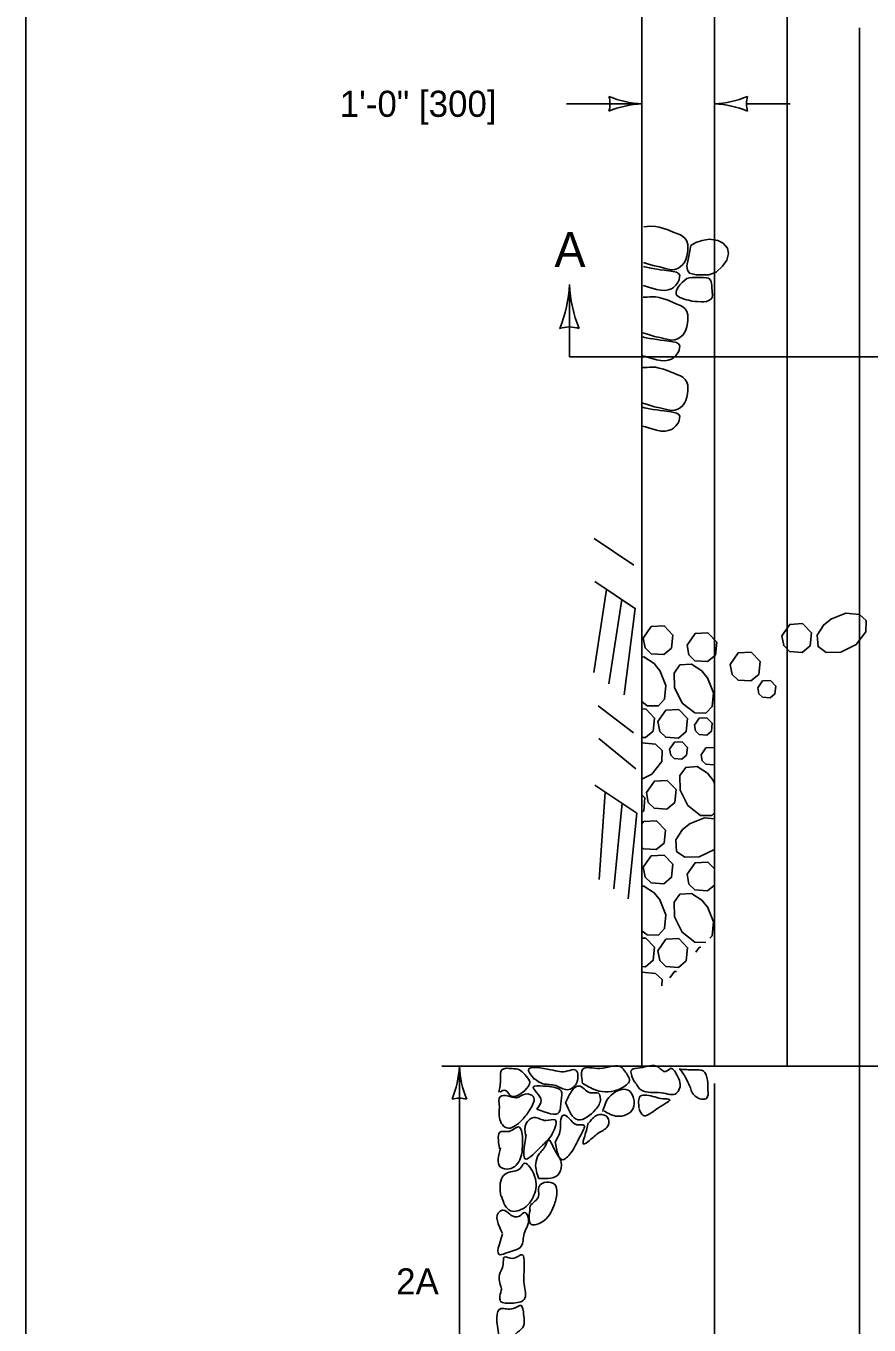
# Model space of a CAD drawing. Extents: x 49991.4 to 50021, y 49987.6 to 50011.4.
# Drawn here: x 49999.384 to 50001.321, y 49993.444 to 49996.429 of the extents above; entities that cross this region are included whole.
import ezdxf

# ---------------------------------------------------------------- set-up
doc = ezdxf.new("R2010")
doc.units = 0
for name, color, linetype in [('Level 1', 7, 'Continuous'), ('Level 2', 7, 'Continuous'), ('Level 3', 7, 'Continuous'), ('Level 6', 7, 'Continuous')]:
    doc.layers.add(name, color=color, linetype=linetype)

msp = doc.modelspace()

# ---------------------------------------------------------------- linework, layer by layer
at = {"layer": 'Level 1'}
for p, q in [((50001.1324, 49997.6503), (50001.1324, 49994.0392)), ((50000.9657, 49997.2058), (50000.9657, 49994.0392)), ((50000.7991, 49997.1899), (50000.7991, 49994.0392)), ((50000.7806, 49995.1902), (50000.6892, 49995.2514)), ((50000.7844, 49995.0903), (50000.6904, 49995.1528)), ((50000.7175, 49995.1348), (50000.6885, 49994.9441)), ((50000.7528, 49995.1114), (50000.7233, 49994.9177)), ((50000.7833, 49995.091), (50000.758, 49994.8927)), ((50000.7796, 49994.805), (50000.6986, 49994.8671)), ((50000.7848, 49994.7221), (50000.7001, 49994.7922)), ((50000.9629, 49994.6962), (50000.9657, 49994.6891)), ((50000.7874, 49994.6204), (50000.691, 49994.685)), ((50000.7146, 49994.6692), (50000.7007, 49994.4685)), ((50000.7533, 49994.6432), (50000.7344, 49994.4465)), ((50000.7874, 49994.6204), (50000.767, 49994.4241)), ((50000.7991, 49994.0392), (50001.7992, 49994.0392))]:
    msp.add_line(p, q, dxfattribs=at)
for points in [[(49999.3835, 49998.9992), (50016.7501, 49998.9992), (50016.7501, 49987.7988), (49999.3835, 49987.7988)], [(50000.9081, 49995.8509), (50000.9024, 49995.8491), (50000.8972, 49995.8453), (50000.8913, 49995.8404), (50000.8864, 49995.8348), (50000.8825, 49995.8292), (50000.8788, 49995.8225), (50000.878, 49995.8171), (50000.878, 49995.8133), (50000.8795, 49995.8104), (50000.8827, 49995.8079), (50000.8862, 49995.8054), (50000.8908, 49995.8037), (50000.8963, 49995.8014), (50000.9017, 49995.8001), (50000.9071, 49995.7992), (50000.9135, 49995.7974), (50000.9206, 49995.796), (50000.9265, 49995.796), (50000.9349, 49995.7956), (50000.9411, 49995.7956), (50000.9477, 49995.7965), (50000.9541, 49995.7992), (50000.9581, 49995.8023), (50000.9603, 49995.8059), (50000.9615, 49995.8099), (50000.9605, 49995.8204), (50000.9598, 49995.8278), (50000.9593, 49995.8332), (50000.9583, 49995.8424), (50000.9561, 49995.8462), (50000.9526, 49995.8496), (50000.9467, 49995.8511), (50000.9396, 49995.8513), (50000.9305, 49995.8516), (50000.9214, 49995.8516), (50000.9145, 49995.8516)]]:
    msp.add_lwpolyline(points, close=True, dxfattribs=at)
for points in [[(50000.8031, 49995.9682), (50000.8113, 49995.9684), (50000.8172, 49995.9691), (50000.8298, 49995.9689), (50000.8389, 49995.9671), (50000.8487, 49995.9644), (50000.8566, 49995.9617), (50000.862, 49995.9595), (50000.8709, 49995.9559), (50000.8793, 49995.9523), (50000.8879, 49995.9492), (50000.8928, 49995.9458), (50000.8987, 49995.9411), (50000.9022, 49995.9348), (50000.9041, 49995.9274), (50000.9046, 49995.9225), (50000.9044, 49995.9154), (50000.9039, 49995.9082), (50000.9019, 49995.9004), (50000.9002, 49995.8927), (50000.8972, 49995.8878), (50000.8926, 49995.8811), (50000.8869, 49995.8759), (50000.8817, 49995.8724), (50000.8743, 49995.8701), (50000.8672, 49995.8695), (50000.8527, 49995.8724), (50000.8401, 49995.8757), (50000.8276, 49995.8782), (50000.8138, 49995.8824), (50000.8025, 49995.8858)], [(50000.954, 49995.9395), (50000.9373, 49995.9368), (50000.923, 49995.9319), (50000.9116, 49995.925), (50000.9067, 49995.9006), (50000.9023, 49995.8786), (50000.9038, 49995.8683), (50000.9082, 49995.8616), (50000.924, 49995.858), (50000.953, 49995.858), (50000.9693, 49995.8638), (50000.9845, 49995.8773), (50000.9944, 49995.8916), (50000.9983, 49995.9064), (50000.9954, 49995.9189), (50000.9855, 49995.9306), (50000.9732, 49995.9368), (50000.954, 49995.9395)], [(50000.8025, 49995.8765), (50000.8052, 49995.8757), (50000.816, 49995.8735), (50000.8244, 49995.8721), (50000.8337, 49995.8708), (50000.8411, 49995.8695), (50000.85, 49995.8686), (50000.866, 49995.8663), (50000.8783, 49995.8636), (50000.8827, 49995.8609), (50000.8862, 49995.8565), (50000.8857, 49995.852), (50000.8845, 49995.8459), (50000.8813, 49995.8399), (50000.8768, 49995.8341), (50000.8719, 49995.8287), (50000.867, 49995.8256), (50000.8596, 49995.8233), (50000.8527, 49995.822), (50000.8428, 49995.8222), (50000.8323, 49995.8242), (50000.8251, 49995.8265), (50000.816, 49995.8287), (50000.8069, 49995.8318), (50000.8021, 49995.833)], [(50000.8019, 49995.8062), (50000.8029, 49995.8064), (50000.8113, 49995.8066), (50000.8172, 49995.8073), (50000.8298, 49995.807), (50000.8389, 49995.8052), (50000.8487, 49995.8026), (50000.8566, 49995.7999), (50000.862, 49995.7976), (50000.8709, 49995.794), (50000.8793, 49995.7905), (50000.8879, 49995.7873), (50000.8928, 49995.784), (50000.8987, 49995.7793), (50000.9022, 49995.773), (50000.9041, 49995.7656), (50000.9046, 49995.7607), (50000.9044, 49995.7535), (50000.9039, 49995.7464), (50000.9019, 49995.7385), (50000.9002, 49995.7309), (50000.8972, 49995.726), (50000.8926, 49995.7193), (50000.8869, 49995.7141), (50000.8817, 49995.7105), (50000.8743, 49995.7083), (50000.8672, 49995.7076), (50000.8527, 49995.7105), (50000.8401, 49995.7139), (50000.8276, 49995.7163), (50000.8138, 49995.7206), (50000.8013, 49995.7244)], [(50000.8013, 49995.715), (50000.8052, 49995.7139), (50000.816, 49995.7116), (50000.8244, 49995.7103), (50000.8337, 49995.709), (50000.8411, 49995.7076), (50000.85, 49995.7067), (50000.866, 49995.7045), (50000.8783, 49995.7018), (50000.8827, 49995.6991), (50000.8862, 49995.6946), (50000.8857, 49995.6902), (50000.8845, 49995.6841), (50000.8813, 49995.6781), (50000.8768, 49995.6722), (50000.8719, 49995.6669), (50000.867, 49995.6637), (50000.8596, 49995.6615), (50000.8527, 49995.6602), (50000.8428, 49995.6604), (50000.8323, 49995.6624), (50000.8251, 49995.6646), (50000.816, 49995.6669), (50000.8069, 49995.67), (50000.8009, 49995.6715)], [(50000.8007, 49995.6442), (50000.8029, 49995.6445), (50000.8113, 49995.6447), (50000.8172, 49995.6454), (50000.8298, 49995.6452), (50000.8389, 49995.6434), (50000.8487, 49995.6407), (50000.8566, 49995.638), (50000.862, 49995.6358), (50000.8709, 49995.6322), (50000.8793, 49995.6286), (50000.8879, 49995.6255), (50000.8928, 49995.6221), (50000.8987, 49995.6174), (50000.9022, 49995.6112), (50000.9041, 49995.6038), (50000.9046, 49995.5988), (50000.9044, 49995.5917), (50000.9039, 49995.5845), (50000.9019, 49995.5767), (50000.9002, 49995.5691), (50000.8972, 49995.5641), (50000.8926, 49995.5574), (50000.8869, 49995.5523), (50000.8817, 49995.5487), (50000.8743, 49995.5464), (50000.8672, 49995.5458), (50000.8527, 49995.5487), (50000.8401, 49995.552), (50000.8276, 49995.5545), (50000.8138, 49995.5588), (50000.8012, 49995.5626), (50000.8001, 49995.563)], [(50000.8, 49995.5536), (50000.8052, 49995.552), (50000.816, 49995.5498), (50000.8244, 49995.5485), (50000.8337, 49995.5471), (50000.8411, 49995.5458), (50000.85, 49995.5449), (50000.866, 49995.5426), (50000.8783, 49995.54), (50000.8827, 49995.5373), (50000.8862, 49995.5328), (50000.8857, 49995.5283), (50000.8845, 49995.5223), (50000.8813, 49995.5162), (50000.8768, 49995.5104), (50000.8719, 49995.505), (50000.867, 49995.5019), (50000.8596, 49995.4997), (50000.8527, 49995.4983), (50000.8428, 49995.4985), (50000.8323, 49995.5006), (50000.8251, 49995.5028), (50000.816, 49995.505), (50000.8069, 49995.5082), (50000.7997, 49995.5099)], [(50001.2331, 49995.0664), (50001.2676, 49995.0801), (50001.2993, 49995.0773), (50001.3144, 49995.063), (50001.3139, 49995.0373), (50001.291, 49995.0081), (50001.2557, 49994.9904), (50001.2224, 49994.9898), (50001.2037, 49995.0032), (50001.2019, 49995.0297), (50001.2171, 49995.0534), (50001.2345, 49995.0673)], [(50000.8019, 49995.0231), (50000.8203, 49995.0493), (50000.8497, 49995.051), (50000.8702, 49995.0298), (50000.8672, 49995.0001), (50000.8491, 49994.9849), (50000.82, 49994.987), (50000.8063, 49995.0003), (50000.8019, 49995.0231)], [(50001.1203, 49995.0283), (50001.1387, 49995.0545), (50001.1681, 49995.0562), (50001.1886, 49995.0349), (50001.1857, 49995.0052), (50001.1675, 49994.9901), (50001.1384, 49994.9922), (50001.1247, 49995.0055), (50001.1203, 49995.0283)], [(50000.9027, 49995.007), (50000.9211, 49995.0333), (50000.9506, 49995.035), (50000.971, 49995.0137), (50000.9681, 49994.984), (50000.9499, 49994.9689), (50000.9208, 49994.971), (50000.9071, 49994.9842), (50000.9027, 49995.007)], [(50001.002, 49994.9624), (50001.0204, 49994.9887), (50001.0499, 49994.9903), (50001.0704, 49994.9691), (50001.0674, 49994.9394), (50001.0492, 49994.9243), (50001.0201, 49994.9264), (50001.0065, 49994.9396), (50001.002, 49994.9624)], [(50000.7991, 49994.9793), (50000.8035, 49994.9796), (50000.8272, 49994.9644), (50000.8411, 49994.947)], [(50000.9496, 49994.9316), (50000.9632, 49994.8971), (50000.9605, 49994.8654), (50000.9462, 49994.8504), (50000.9205, 49994.8509), (50000.8912, 49994.8737), (50000.8736, 49994.9091), (50000.873, 49994.9423), (50000.8863, 49994.9611), (50000.9128, 49994.9629), (50000.9366, 49994.9477), (50000.9505, 49994.9303)], [(50000.8402, 49994.9484), (50000.8539, 49994.9139), (50000.8512, 49994.8822), (50000.8368, 49994.8671), (50000.8111, 49994.8676), (50000.7991, 49994.877)], [(50001.0654, 49994.9087), (50001.0764, 49994.9244), (50001.0941, 49994.9254), (50001.1064, 49994.9127), (50001.1046, 49994.8948), (50001.0937, 49994.8858), (50001.0762, 49994.887), (50001.068, 49994.895), (50001.0654, 49994.9087)], [(50000.7991, 49994.8597), (50000.8076, 49994.8602), (50000.8281, 49994.839), (50000.8251, 49994.8092), (50000.8069, 49994.7941), (50000.7991, 49994.7947)], [(50000.8356, 49994.8312), (50000.854, 49994.8574), (50000.8835, 49994.8591), (50000.904, 49994.8379), (50000.901, 49994.8081), (50000.8828, 49994.793), (50000.8537, 49994.7951), (50000.8401, 49994.8084), (50000.8356, 49994.8312)], [(50000.9195, 49994.8231), (50000.9306, 49994.8388), (50000.9482, 49994.8398), (50000.9605, 49994.8271), (50000.9587, 49994.8092), (50000.9478, 49994.8002), (50000.9304, 49994.8014), (50000.9222, 49994.8094), (50000.9195, 49994.8231)], [(50000.7991, 49994.7819), (50000.8301, 49994.7792), (50000.8452, 49994.7649), (50000.8447, 49994.7392), (50000.8218, 49994.7099), (50000.7991, 49994.6986)], [(50000.8624, 49994.7677), (50000.8735, 49994.7835), (50000.8912, 49994.7845), (50000.9034, 49994.7717), (50000.9017, 49994.7539), (50000.8908, 49994.7448), (50000.8733, 49994.7461), (50000.8651, 49994.754), (50000.8624, 49994.7677)], [(50000.9351, 49994.7548), (50000.9461, 49994.7705), (50000.9638, 49994.7715), (50000.9657, 49994.7695)], [(50000.9657, 49994.7338), (50000.9634, 49994.7318), (50000.946, 49994.7331), (50000.9377, 49994.7411), (50000.9351, 49994.7547)], [(50000.9657, 49994.6215), (50000.9596, 49994.615), (50000.9338, 49994.6155), (50000.9046, 49994.6383), (50000.887, 49994.6737), (50000.8864, 49994.7069), (50000.8997, 49994.7257), (50000.9262, 49994.7275), (50000.9499, 49994.7123), (50000.9638, 49994.6948)], [(50000.8091, 49994.6681), (50000.8275, 49994.6944), (50000.857, 49994.696), (50000.8774, 49994.6748), (50000.8745, 49994.6451), (50000.8563, 49994.63), (50000.8272, 49994.6321), (50000.8135, 49994.6453), (50000.8091, 49994.6681)], [(50000.7991, 49994.6627), (50000.8059, 49994.6556), (50000.803, 49994.6258), (50000.7991, 49994.6226)], [(50000.7991, 49994.5957), (50000.8029, 49994.6012), (50000.8324, 49994.6029), (50000.8529, 49994.5817), (50000.8499, 49994.5519), (50000.8317, 49994.5368), (50000.8026, 49994.5389), (50000.7991, 49994.5424)], [(50000.9083, 49994.5959), (50000.9428, 49994.6096), (50000.9657, 49994.6076)], [(50000.9657, 49994.5374), (50000.9308, 49994.52), (50000.8975, 49994.5194), (50000.8788, 49994.5327), (50000.877, 49994.5592), (50000.8922, 49994.5829), (50000.9097, 49994.5968)], [(50000.8019, 49994.4964), (50000.8203, 49994.5227), (50000.8497, 49994.5244), (50000.8702, 49994.5031), (50000.8672, 49994.4734), (50000.8491, 49994.4583), (50000.82, 49994.4604), (50000.8063, 49994.4736), (50000.8019, 49994.4964)], [(50000.9027, 49994.4804), (50000.9211, 49994.5066), (50000.9506, 49994.5083), (50000.9657, 49994.4925)], [(50000.7991, 49994.4526), (50000.8035, 49994.4529), (50000.8272, 49994.4377), (50000.8411, 49994.4203)], [(50000.9657, 49994.4554), (50000.9499, 49994.4422), (50000.9208, 49994.4443), (50000.9071, 49994.4576), (50000.9027, 49994.4804)], [(50000.8402, 49994.4217), (50000.8539, 49994.3872), (50000.8512, 49994.3555), (50000.8368, 49994.3404), (50000.8111, 49994.3409), (50000.7991, 49994.3504)], [(50000.9456, 49994.3237), (50000.9205, 49994.3242), (50000.8912, 49994.3471), (50000.8736, 49994.3824), (50000.873, 49994.4157), (50000.8863, 49994.4344), (50000.9128, 49994.4362), (50000.9366, 49994.421), (50000.9505, 49994.4036)], [(50000.9496, 49994.405), (50000.9632, 49994.3705), (50000.9605, 49994.3388), (50000.9553, 49994.3333)], [(50000.7991, 49994.3331), (50000.8076, 49994.3335), (50000.8281, 49994.3123), (50000.8251, 49994.2826), (50000.8069, 49994.2675), (50000.7991, 49994.268)], [(50000.8356, 49994.3045), (50000.854, 49994.3307), (50000.8835, 49994.3324), (50000.904, 49994.3112), (50000.901, 49994.2815), (50000.8828, 49994.2663), (50000.8537, 49994.2684), (50000.8401, 49994.2817), (50000.8356, 49994.3045)], [(50000.9228, 49994.3012), (50000.9306, 49994.3121), (50000.9341, 49994.3123)], [(50000.7991, 49994.2552), (50000.8301, 49994.2525), (50000.8452, 49994.2382), (50000.8449, 49994.2239)], [(50000.863, 49994.2419), (50000.8735, 49994.2568), (50000.8783, 49994.2571)]]:
    msp.add_lwpolyline(points, dxfattribs=at)
for points in [[(50000.4702, 49993.9795), (50000.4743, 49994.0101), (50000.4771, 49994.0309), (50000.5007, 49994.0337), (50000.5174, 49994.0309), (50000.5299, 49994.0198), (50000.541, 49994.0031), (50000.5299, 49993.9836), (50000.4952, 49993.9725), (50000.4855, 49993.9836), (50000.473, 49993.9795)], [(50000.5521, 49994.0087), (50000.5382, 49994.0309), (50000.5896, 49994.0309), (50000.6285, 49994.0281), (50000.6452, 49994.0309), (50000.6508, 49994.0059), (50000.6271, 49993.985), (50000.6008, 49993.9948), (50000.5716, 49993.9989), (50000.5521, 49994.0101)], [(50000.6619, 49994.002), (50000.6633, 49994.0326), (50000.7022, 49994.034), (50000.7536, 49994.0354), (50000.7591, 49994.0284), (50000.7702, 49994.0062), (50000.7508, 49993.9881), (50000.6938, 49993.984), (50000.6619, 49994.0006)], [(50000.7814, 49994.0032), (50000.7758, 49994.031), (50000.7939, 49994.0352), (50000.8369, 49994.0366), (50000.8536, 49994.0269), (50000.8647, 49994.0338), (50000.8814, 49994.0144), (50000.8869, 49993.9977), (50000.8786, 49993.9768), (50000.8439, 49993.9782), (50000.798, 49993.9838), (50000.7827, 49994.0032)], [(50000.8842, 49994.0324), (50000.9189, 49994.031), (50000.9397, 49994.0282), (50000.9494, 49994.0074), (50000.9508, 49993.9838), (50000.9481, 49993.9657), (50000.9217, 49993.9699), (50000.9092, 49993.9921), (50000.8994, 49994.013), (50000.8869, 49994.0324)], [(50000.4716, 49993.9446), (50000.4743, 49993.9696), (50000.4896, 49993.971), (50000.5105, 49993.9668), (50000.5313, 49993.9751), (50000.5494, 49993.9696), (50000.5424, 49993.9404), (50000.523, 49993.9154), (50000.4882, 49993.8973), (50000.4757, 49993.9085), (50000.4716, 49993.9432)], [(50000.5577, 49993.9407), (50000.5674, 49993.9602), (50000.5577, 49993.9782), (50000.5494, 49993.9907), (50000.573, 49993.9935), (50000.5966, 49993.9907), (50000.6133, 49993.9824), (50000.6133, 49993.9602), (50000.6091, 49993.9338), (50000.5577, 49993.9407)], [(50000.623, 49993.9546), (50000.6327, 49993.9741), (50000.6411, 49993.9866), (50000.6536, 49993.9935), (50000.6799, 49993.9782), (50000.6994, 49993.9768), (50000.7036, 49993.9643), (50000.6924, 49993.9393), (50000.6522, 49993.9157), (50000.623, 49993.956)], [(50000.7091, 49993.9352), (50000.723, 49993.9671), (50000.7675, 49993.9838), (50000.7786, 49993.9421), (50000.7425, 49993.924), (50000.7119, 49993.9366)], [(50000.7925, 49993.9421), (50000.7952, 49993.9699), (50000.8286, 49993.9685), (50000.848, 49993.9643), (50000.8619, 49993.9629), (50000.8369, 49993.9435), (50000.8008, 49993.9268), (50000.7925, 49993.9407)], [(50000.5313, 49993.881), (50000.5327, 49993.9074), (50000.5507, 49993.9213), (50000.5785, 49993.9143), (50000.5994, 49993.9157), (50000.5938, 49993.8852), (50000.5674, 49993.8546), (50000.5327, 49993.8254), (50000.5327, 49993.8824)], [(50000.5994, 49993.8643), (50000.6119, 49993.8963), (50000.6119, 49993.9115), (50000.6188, 49993.9268), (50000.6313, 49993.9199), (50000.6494, 49993.9046), (50000.6661, 49993.9032), (50000.6591, 49993.8824), (50000.6383, 49993.8435), (50000.6174, 49993.824), (50000.5994, 49993.8657)], [(50000.6772, 49993.9088), (50000.7022, 49993.9282), (50000.7202, 49993.9213), (50000.7216, 49993.9032), (50000.7008, 49993.8865), (50000.6786, 49993.8685), (50000.6647, 49993.8602), (50000.6674, 49993.8782), (50000.6758, 49993.9088)], [(50000.4716, 49993.849), (50000.4757, 49993.8893), (50000.4938, 49993.8893), (50000.5174, 49993.899), (50000.523, 49993.8865), (50000.5244, 49993.856), (50000.5202, 49993.8282), (50000.4938, 49993.8032), (50000.4743, 49993.8074), (50000.4743, 49993.8518)], [(50000.5619, 49993.7808), (50000.5549, 49993.8155), (50000.5619, 49993.8364), (50000.5771, 49993.8558), (50000.5841, 49993.8697), (50000.598, 49993.8475), (50000.6133, 49993.8183), (50000.6091, 49993.7933), (50000.5619, 49993.7808)], [(50000.4747, 49993.7402), (50000.4788, 49993.7847), (50000.49, 49993.7944), (50000.5191, 49993.8041), (50000.5275, 49993.8152), (50000.5497, 49993.793), (50000.5525, 49993.7471), (50000.5288, 49993.7138), (50000.4969, 49993.7069), (50000.4761, 49993.7402)], [(50000.5424, 49993.7058), (50000.541, 49993.7141), (50000.5605, 49993.7377), (50000.5633, 49993.7641), (50000.598, 49993.7683), (50000.6035, 49993.7475), (50000.5966, 49993.7183), (50000.5688, 49993.6808), (50000.5452, 49993.6752), (50000.541, 49993.7072)], [(50000.4785, 49993.6544), (50000.473, 49993.7058), (50000.4799, 49993.7086), (50000.4952, 49993.6989), (50000.5174, 49993.6947), (50000.5299, 49993.703), (50000.5382, 49993.6891), (50000.5285, 49993.6544), (50000.5216, 49993.6252), (50000.491, 49993.6113), (50000.473, 49993.6058), (50000.4785, 49993.653)], [(50000.4757, 49993.5294), (50000.4716, 49993.5599), (50000.4799, 49993.5835), (50000.4827, 49993.6002), (50000.5021, 49993.5974), (50000.5244, 49993.6058), (50000.5285, 49993.5863), (50000.5285, 49993.5377), (50000.5285, 49993.503), (50000.4994, 49993.4946), (50000.4743, 49993.4988), (50000.4771, 49993.528)], [(50000.4702, 49993.4196), (50000.4757, 49993.4821), (50000.5035, 49993.4821), (50000.5216, 49993.4891), (50000.5271, 49993.4682), (50000.5271, 49993.4419), (50000.4994, 49993.4113), (50000.4924, 49993.3904), (50000.4702, 49993.3918), (50000.4702, 49993.4196)]]:
    msp.add_spline(points, degree=3, dxfattribs=at)
at = {"layer": 'Level 3'}
for p, q in [((50000.6257, 49996.2507), (50000.7991, 49996.2507)), ((50001.0393, 49996.2507), (50001.1393, 49996.2507)), ((50000.3394, 49994.0392), (50000.9257, 49994.0392)), ((50000.3794, 49993.0499), (50000.3794, 49994.0392)), ((50000.9657, 49993.9992), (50000.9657, 49992.8309))]:
    msp.add_line(p, q, dxfattribs=at)
for centre, radius, start, end in [((50000.8082, 49996.4729), 0.2223, 247.456, 267.6395), ((50000.6709, 49996.2507), 0.0548, 342.1388, 17.8612), ((50000.8106, 49996.018), 0.233, 92.8273, 112.0772), ((50000.9566, 49996.4729), 0.2223, 272.3605, 292.544), ((50000.9543, 49996.018), 0.233, 67.9228, 87.1727), ((50001.094, 49996.2507), 0.0548, 162.1388, 197.8612), ((50000.1573, 49994.0484), 0.2223, 337.456, 357.6395), ((50000.6122, 49994.0507), 0.233, 182.8273, 202.0772), ((50000.3794, 49993.911), 0.0548, 72.1388, 107.8612)]:
    msp.add_arc(centre, radius, start, end, dxfattribs=at)
at = {"layer": 'Level 6'}
for p, q in [((50001.2991, 49993.0109), (50001.2991, 49996.4249)), ((50000.6323, 49995.669), (50000.6323, 49995.8357)), ((50000.6323, 49995.669), (50001.9659, 49995.669))]:
    msp.add_line(p, q, dxfattribs=at)
for centre, radius, start, end in [((50000.3362, 49995.8479), 0.2964, 337.456, 357.6395), ((50000.9426, 49995.851), 0.3107, 182.8273, 202.0772), ((50000.6323, 49995.6648), 0.073, 72.1388, 107.8612)]:
    msp.add_arc(centre, radius, start, end, dxfattribs=at)

# ---------------------------------------------------------------- texts
at = {"layer": 'Level 2'}
for s, height, p in [('1\'-0" [300]', 0.06, (50000.1045, 49996.2207)), ('A', 0.08, (50000.598, 49995.8757)), ('2A', 0.06, (50000.2341, 49993.5146))]:
    msp.add_text(s, height=height, dxfattribs=at).set_placement(p)

doc.saveas('drawing.dxf')
